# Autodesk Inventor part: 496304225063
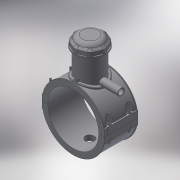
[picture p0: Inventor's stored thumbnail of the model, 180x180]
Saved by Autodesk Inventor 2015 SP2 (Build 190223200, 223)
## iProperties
Created: 2017-07
Part Number: 496304225063
Material: Generic
Description: PLASSON TAPPING SADDLE 225x63
Document SubType Name: Modeling
Designer: KIM
Mass: 1713.83 g
Surface Area: 3743.62 cm^2
Volume: 1713.83 cm^3
Density: 1 g/cm^3
Appearance: Default
Author: KIM
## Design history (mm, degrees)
derived "496304.ipt"
feature "Solid1::496304.ipt"
feature "Solid2::496304.ipt"
feature "Solid4::496304.ipt"
feature "Solid5::496304.ipt"
tag "TaggingFeature1" dims "B_" = 227
body "Solid1"
body "Solid2"
other parameters: "d_" = 225, "L_" = 176, "d_t" = 6, "H_2" = 177, "H_1" = 64, "d_1" = 63, "H_" = 175, "d1" = 256.5, "d148" = 3.375, "d160" = 3.375, "d169" = 3.375, "d192" = 6.3, "d0" = 225, "d2" = 295.1, "d3" = 56.25, "d4" = 176, "d5" = 0, "d6" = 0.1, "d8" = 0, "d19" = 6, "d20" = 6, "d21" = 105.6, "d23" = 0, "d24" = 52.8, "d26" = 0, "d29" = 3, "d30" = 75, "d31" = 6, "d32" = 0, "d33" = 0, "d34" = 0.6, "d40" = 133.38, "d43" = 0, "d45" = 0, "d47" = 233.85, "d70" = 15, "d72" = 0, "d73" = 6, "d75" = 5, "d76" = 0, "d77" = 11.25, "d78" = 142.5, "d79" = 15, "d80" = 70.4, "d82" = 5 deg, "d84" = 4, "d85" = 14, "d86" = 0, "d87" = 3, "d88" = 0, "d89" = 1, "d90" = 1, "d91" = 140.8, "d92" = 0, "d93" = 0.5, "d94" = 118.42105, "d96" = 261.63, "d97" = 3.52, "d98" = 0, "d102" = 2.25, "d120" = 140 deg, "d121" = 24.228, "d122" = 20 deg, "d123" = 513, "d124" = 153.9, "d126" = 0, "d143" = 231.75, "d145" = 24.23077, "d149" = 3.375, "d150" = 26.65385, "d153" = 176, "d154" = 0, "d156" = 128.25, "d157" = 160 deg, "d159" = 6.3, "d161" = 3.375, "d162" = 105.6, "d163" = 0, "d164" = 112.5, "d167" = 22.5, "d168" = 125.12195, "d170" = 3.375, "d172" = 0, "d173" = 1, "d175" = 112.5, "d176" = 20 deg, "d177" = 15.75, "d178" = 31.5, "d180" = 0, "d183" = 12.6, "d184" = 12.6, "d185" = 57.2, "d186" = 57.2, "d187" = 128.25, "d188" = 9.45, "d189" = 15.75, "d190" = 0, "d191" = 192.375, "d193" = 6.3, "d194" = 6.16, "d195" = 90 deg, "d197" = 0, "d199" = 0, "d200" = 15.75, "d202" = 0, "d203" = 177, "d204" = 85.5, "d205" = 63, "d206" = 76.5, "d207" = 132.75, "d208" = 138.06, "d209" = 164.61, "d210" = 77.4, "d212" = 72, "d213" = 29.25, "d216" = 0, "d217" = 22.5, "d218" = 22.5, "d219" = 4.5, "d222" = 225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
